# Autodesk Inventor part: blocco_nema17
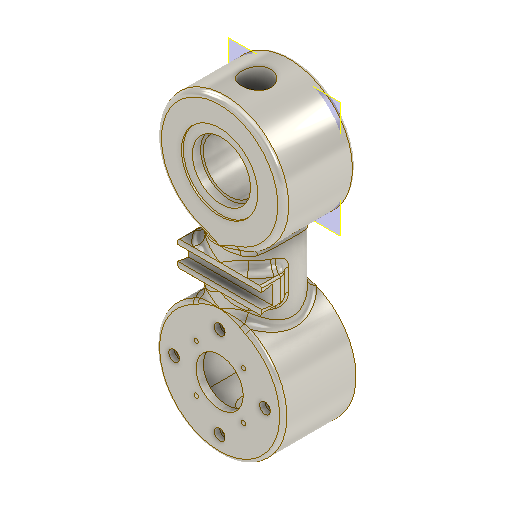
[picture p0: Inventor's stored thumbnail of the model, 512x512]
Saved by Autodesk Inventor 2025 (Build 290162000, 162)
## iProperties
Created: 2025-05
Part Number: blocco_nema17
Material: Titanio
Document SubType Name: Modeling
Designer: 18907419
Density: 4.51 g/cm^3
Appearance: Titanio
alezza: 50,000 mm
Author: 18907419
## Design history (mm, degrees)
sketch "Schizzo1"
  geometry: C1 r 35 at (0, 0); 1 further point
  constraints: 1 centre point, 1 coincident
  dimensions: "d0" = 70 diameter of C1
extrude "Estrusione1" new body sketch "Schizzo1" stored distance "d1" = 40; taper "d2" = 0 deg
sketch "Schizzo2"
  geometry: L1 (-35, -20)-(35, -20) reference; L2 (35, 20)-(-35, 20) reference; L3 (35, -20)-(35, 20) reference; L4 (-35, -20)-(-35, 20) reference; C1 r 20 at (0, 0); 1 further point
  constraints: 1 centre point, 1 coincident
  dimensions: "d52" = 40 diameter of C1
extrude "Estrusione2" join sketch "Schizzo2" taper "d4" = 0 deg
sketch "Schizzo7"
  geometry: C1 r 8 at (0, 0); 1 further point
  constraints: 1 centre point, 1 coincident
  dimensions: "d19" = 16 diameter of C1
extrude "Estrusione7" cut sketch "Schizzo7" distance "d20" = 95.5; taper "d21" = 0 deg
sketch "Schizzo12"
  geometry: L1 (-21.05, 21.05)-(21.05, 21.05); L2 (21.05, 21.05)-(21.05, -21.05); L3 (21.05, -21.05)-(-21.05, -21.05); L4 (-21.05, -21.05)-(-21.05, 21.05); L5 (-21.05, 21.05)-(21.05, -21.05); L6 (21.05, 21.05)-(-21.05, -21.05); 1 further point
  constraints: 12 end point, 2 midpoint, 2 parallel, 1 horizontal, 1 perpendicular
  dimensions: "d38" = 42.1 distance of L2.end L3.end; "d39" = 42.1 distance of L1.end L2.end
extrude "Estrusione11" cut sketch "Schizzo12" distance "d40" = 60; taper "d41" = 0 deg
mirror "Speculare2"
sketch "Schizzo13"
  geometry: C1 r 16 at (0, 0); 1 further point
  constraints: 1 centre point
  dimensions: "d42" = 32 diameter of C1
extrude "Estrusione12" cut sketch "Schizzo13" extent not by distance; stored distance "d43" = 32; taper "d44" = 0 deg
mirror "Speculare3"
sketch "Schizzo18"
  geometry: L1 (-21.05, -21.05)-(-21.05, 21.05) reference; L2 (-21.05, 21.05)-(21.05, 21.05) reference; L3 (21.05, 21.05)-(21.05, -21.05) reference; L4 (21.05, -21.05)-(-21.05, -21.05) reference; C1 r 13 at (0, 0); C2 r 1.23 at (13.1, 13.1) reference; C3 r 1.23 at (13.1, -12.9) reference; C4 r 1.23 at (-12.9, -12.9) reference; C5 r 1.23 at (-12.9, 13.1) reference; 3 further points
  constraints: 1 centre point, 1 coincident, 1 vertical alignment
  dimensions: "d63" = 26 diameter of C1
  node "Linea chiusa proiettata5"
  node "Riferimento1"
  node "Riferimento2"
  node "Riferimento3"
  node "Riferimento4"
node "Piano di lavoro2"
extrude "Estrusione16" join sketch "Schizzo18" stored distance "d64" = 3; taper "d65" = 0 deg
sketch "Schizzo19"
  geometry: C1 r 1.7 at (0, 25) reference; 1 further point
hole "Foro3" sketch "Schizzo19" at (0, 25) diameter "d66" = 3.4; stored, may be unused: countersink angle "d70" = 90 deg, drill point angle "d72" = 118 deg; dims "d67" = 6, "d68" = 6.3, "d69" = 3.4, "d71" = 8
sketch "Schizzo20"
  geometry: C1 r 1.7 at (0, 25) reference; 2 further points
  constraints: 1 coincident
hole "Foro4" sketch "Schizzo20" at (0, 25) diameter "d76" = 3.4; stored, may be unused: countersink angle "d80" = 90 deg, drill point angle "d82" = 118 deg; dims "d77" = 6, "d78" = 6, "d79" = 3, "d81" = 8
pattern_circular "Serie circolare2" dims "d84" = 360 deg
fillet "Raccordo2" dims "d88" = 3
fillet "Raccordo3" dims "d89" = 5
fillet "Raccordo4" dims "d90" = 2
fillet "Raccordo5" dims "d91" = 2
node "Piano di lavoro3"
sketch "Schizzo23"
  geometry: L1 (0, 0)-(0, 100); L2 (20, 31.225)-(20, 68.775) reference; L3 (-23, 57)-(23, 57); L4 (23, 57)-(23, 43); L5 (23, 43)-(-23, 43); L6 (-23, 43)-(-23, 57); L7 (-23, 57)-(23, 43); L8 (23, 57)-(-23, 43); C1 r 10.7 at (0, 0) reference; C2 r 16 at (0, 100) reference; 2 further points
  constraints: 14 end point, 3 midpoint, 2 parallel, 1 coincident, 1 horizontal, 1 perpendicular, 1 vertical
  dimensions: "d104" = 46 distance of L4.end L5.end; "d105" = 14 distance of L3.end L4.end
extrude "Estrusione19" join sketch "Schizzo23" distance "d99" = 7; taper "d101" = 0 deg; dims "d100" = 6, "d102" = 0
fillet "Raccordo6" dims "d106" = 5
fillet "Raccordo7" dims "d107" = 5
sketch "Schizzo24"
  geometry: L1 (-10.38, 0)-(-10.38, 14) reference; L2 (-10.38, 0)-(0, 0) reference; L3 (0, 14)-(0, 0) reference; L4 (-10.38, 14)-(0, 14) reference; L5 (0, 7)-(-10.38, 7); L6 (0, 11)-(-6, 12.058); L7 (-6, 12.058)-(-6, 7); L8 (0, 3)-(-6, 1.942); L9 (-6, 1.942)-(-6, 7); L10 (0, 14)-(0, 0) reference; 3 further points
  constraints: 10 end point, 3 midpoint, 2 point on line, 2 symmetric about line, 1 perpendicular
  dimensions: "d108" = 6 distance between parallel lines of L7 L3; "d109" = 80 deg angle of L7 L6; "d113" = 4 distance of point (0, 7) L6.start
extrude "Estrusione20" cut sketch "Schizzo24" extent not by distance; stored distance "d110" = 0; taper "d111" = 0 deg
node "Piano di lavoro4"
sketch "Schizzo25"
  geometry: C1 r 14.5 at (0, 0); C2 r 16 at (0, 0) reference; 1 further point
  constraints: 1 centre point
  dimensions: "d115" = 29 diameter of C1
extrude "Estrusione21" join sketch "Schizzo25" distance "d116" = 30; taper "d117" = 0 deg
sketch "Schizzo26"
  geometry: C1 r 21 at (0, 0); 1 further point
  constraints: 1 centre point
  dimensions: "d118" = 42 diameter of C1
extrude "Estrusione22" cut sketch "Schizzo26" distance "d119" = 1; taper "d120" = 0 deg
fillet "Raccordo9" dims "d121" = 1
fillet "Raccordo10" dims "d122" = 5
node "Solido1"
node "Linea chiusa proiettata1"
node "Riferimento5"
node "Riferimento7"
node "Linea chiusa proiettata7"
other parameters: "d92" = 13, "d114" = -4.5
